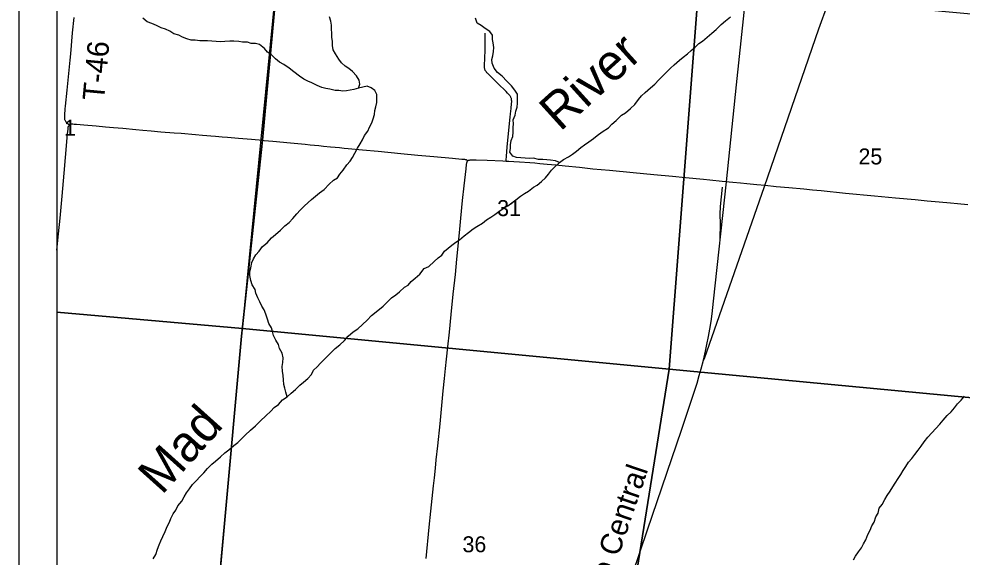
# Model space of a CAD drawing. Extents: x 831 to 1552, y 430 to 870.
# Drawn here: x 943.77 to 993.28, y 749.13 to 777.36 of the extents above; entities that cross this region are included whole.
import ezdxf

# ---------------------------------------------------------------- set-up
doc = ezdxf.new("R2010")
doc.units = 0
for name, color, linetype in [('GM_X_Corporation', 7, 'Continuous'), ('GM_X_County_Road', 7, 'Continuous'), ('GM_X_Major_River', 7, 'Continuous'), ('GM_X_Major_River_Text', 7, 'Continuous'), ('GM_X_Minor_River', 7, 'Continuous'), ('GM_X_Rail_Line', 7, 'Continuous'), ('GM_X_Rail_Line_Text', 7, 'Continuous'), ('GM_X_Section_Text', 7, 'Continuous'), ('GM_X_Township_Road', 7, 'Continuous'), ('GM_X_Township_Road_Text', 7, 'Continuous'), ('SH_Data', 7, 'Continuous')]:
    doc.layers.add(name, color=color, linetype=linetype)

msp = doc.modelspace()

# ---------------------------------------------------------------- linework, layer by layer
at = {"layer": 'GM_X_Corporation'}
for points in [[(958.1, 786.938), (945.766, 786.938), (945.766, 741.831), (953.653, 740.871), (955.451, 760.717), (956.56, 771.006), (957.479, 781.045), (957.492, 781.063), (957.507, 781.085), (957.522, 781.111), (957.532, 781.136), (957.541, 781.164), (957.55, 781.197), (957.556, 781.228), (957.562, 781.276), (957.568, 781.33), (957.577, 781.435), (957.589, 781.599), (957.656, 782.366), (957.749, 783.356), (957.89, 784.782), (957.984, 785.755), (958.044, 786.336)], [(945.766, 781.984), (945.766, 761.978), (955.51, 761.115), (957.457, 780.993)], [(979.447, 778.955), (977.893, 758.996), (955.51, 761.115), (957.457, 780.993)], [(998.895, 777.157), (996.953, 757.185), (977.893, 758.996), (979.447, 778.955)], [(945.766, 761.978), (945.766, 741.664), (953.634, 740.857), (955.51, 761.115)], [(977.893, 758.996), (974.695, 738.984), (953.634, 740.857), (955.51, 761.115)], [(996.953, 757.185), (994.975, 737.085), (974.695, 738.984), (977.893, 758.996)]]:
    msp.add_lwpolyline(points, close=True, dxfattribs=at)
msp.add_lwpolyline([(957.479, 781.045), (956.56, 771.006), (955.451, 760.717), (953.653, 740.871), (952.689, 730.885), (949.971, 703.401), (947.763, 681.071), (945.766, 658.183), (945.766, 650.938), (1069.909, 650.938), (1070.34, 654.531), (1072.813, 675.454), (1078.126, 715.958), (1081.227, 740.59), (1081.766, 744.853), (1081.766, 786.938)], dxfattribs=at)
at = {"layer": 'GM_X_County_Road'}
for points in [[(945.766, 765.229), (945.854, 766.095), (945.934, 766.917), (946.044, 768.07), (946.148, 769.277), (946.215, 770.089), (946.326, 771.327), (946.346, 771.583), (946.351, 771.628), (946.353, 771.651), (946.357, 771.674), (946.362, 771.692), (946.366, 771.707), (946.371, 771.72), (946.377, 771.732), (946.384, 771.743), (946.393, 771.755), (946.402, 771.764), (946.422, 771.782)], [(946.422, 771.782), (946.441, 771.798), (946.456, 771.81), (946.473, 771.825), (946.486, 771.832), (946.5, 771.838), (946.512, 771.843), (946.532, 771.848), (946.553, 771.85), (946.601, 771.849), (946.665, 771.846), (946.79, 771.838), (947.173, 771.806), (947.819, 771.751), (948.31, 771.704), (948.741, 771.667), (949.215, 771.626), (949.907, 771.565), (950.273, 771.532), (950.706, 771.491), (951.224, 771.445), (951.911, 771.39), (952.283, 771.361), (953.031, 771.3), (953.407, 771.269), (953.638, 771.249), (953.841, 771.231), (954.093, 771.208), (954.431, 771.18), (954.709, 771.155), (955.296, 771.104), (955.973, 771.048), (956.565, 770.995)], [(956.565, 770.995), (956.634, 770.989), (957.088, 770.948), (958.025, 770.863), (958.793, 770.787), (959.048, 770.762), (959.516, 770.718), (959.76, 770.693), (960.126, 770.656), (960.368, 770.631), (960.587, 770.608), (960.833, 770.585), (961.055, 770.562), (961.805, 770.491), (962.622, 770.417), (963.822, 770.301), (964.701, 770.217), (965.555, 770.138), (966.519, 770.052), (967.014, 770.01), (967.074, 770.005), (967.148, 769.998), (967.196, 769.992), (967.217, 769.988), (967.238, 769.982), (967.254, 769.975), (967.268, 769.967), (967.283, 769.955), (967.298, 769.943), (967.332, 769.913)], [(965.136, 749.053), (965.307, 750.7), (965.394, 751.549), (965.527, 752.866), (965.575, 753.296), (965.629, 753.789), (965.677, 754.235), (965.749, 754.963), (965.871, 756.122), (965.93, 756.698), (966.042, 757.844), (966.106, 758.493), (966.157, 759.032), (966.211, 759.516), (966.282, 760.165), (966.367, 760.934), (966.461, 761.862), (966.57, 762.922), (966.677, 763.961), (966.755, 764.755), (966.861, 765.784), (966.918, 766.338), (966.971, 766.915), (967.058, 767.829), (967.143, 768.597), (967.241, 769.502), (967.265, 769.729), (967.27, 769.765), (967.275, 769.792), (967.283, 769.827), (967.292, 769.853), (967.301, 769.873), (967.311, 769.889), (967.322, 769.903), (967.332, 769.913)], [(967.332, 769.913), (967.353, 769.931), (967.373, 769.942), (967.394, 769.95), (967.42, 769.957), (967.447, 769.962), (967.479, 769.965), (967.532, 769.967), (967.61, 769.965), (967.768, 769.962), (968.344, 769.942), (969.174, 769.913), (969.338, 769.905)], [(969.338, 769.905), (969.486, 769.898), (969.748, 769.883), (970.037, 769.866), (970.583, 769.83), (970.841, 769.809), (971.102, 769.784), (971.503, 769.743), (971.942, 769.702), (972.444, 769.651), (973.197, 769.576), (973.897, 769.503), (974.765, 769.418), (976.011, 769.301), (977.087, 769.199), (978.076, 769.107), (978.752, 769.04), (979.699, 768.947), (980.025, 768.915), (980.685, 768.851), (981.234, 768.798), (981.647, 768.758), (981.979, 768.726), (982.497, 768.675), (982.934, 768.632), (983.507, 768.576), (984.174, 768.512), (984.96, 768.439), (985.422, 768.395), (985.872, 768.351), (987.155, 768.226), (988.672, 768.081), (989.772, 767.979), (990.808, 767.884), (991.436, 767.825), (992.072, 767.764), (992.667, 767.708), (993.037, 767.675), (993.579, 767.622)]]:
    msp.add_lwpolyline(points, dxfattribs=at)
at = {"layer": 'GM_X_Major_River'}
for points in [[(968.756, 767.099), (968.965, 767.253), (969.19, 767.421), (969.429, 767.559), (969.647, 767.72), (969.856, 767.874), (970.097, 768.057), (970.314, 768.21), (970.514, 768.326), (970.771, 768.532), (970.979, 768.647), (971.205, 768.831), (971.408, 769.023), (971.573, 769.224), (971.731, 769.425), (971.919, 769.625), (972.144, 769.823), (972.354, 769.985), (972.616, 770.122), (972.833, 770.26), (973.035, 770.421), (973.26, 770.613), (973.462, 770.759), (973.679, 770.92), (973.919, 771.08), (974.122, 771.249), (974.385, 771.44), (974.71, 771.643), (974.882, 771.836), (975.116, 772.027), (975.405, 772.308), (975.613, 772.431), (975.863, 772.667), (976.089, 772.874), (976.294, 773.127), (976.444, 773.32), (976.646, 773.505), (976.927, 773.748), (977.145, 773.939), (977.364, 774.169), (977.544, 774.361), (977.74, 774.554), (977.966, 774.775), (978.161, 774.952), (978.434, 775.203), (978.628, 775.35), (978.853, 775.526), (979.048, 775.695), (979.243, 775.857), (979.454, 776.064), (979.647, 776.195), (979.888, 776.401), (980.13, 776.615), (980.371, 776.806), (980.629, 777.065), (980.862, 777.263), (981.119, 777.477)], [(950.823, 749.04), (950.952, 749.272), (951.043, 749.543), (951.126, 749.783), (951.223, 749.978), (951.328, 750.211), (951.442, 750.473), (951.549, 750.736), (951.669, 750.961), (951.751, 751.164), (951.872, 751.396), (951.999, 751.59), (952.104, 751.815), (952.324, 752.059), (952.437, 752.284), (952.564, 752.5), (952.715, 752.716), (952.881, 752.947), (953.084, 753.154), (953.257, 753.347), (953.476, 753.553), (953.665, 753.783), (953.891, 754.004), (954.086, 754.166), (954.35, 754.386), (954.584, 754.6), (954.793, 754.753), (955.043, 754.982), (955.253, 755.15), (955.448, 755.335), (955.636, 755.534), (955.924, 755.784), (956.189, 756.012), (956.455, 756.278), (956.736, 756.544), (956.993, 756.779), (957.166, 756.972), (957.391, 757.14), (957.61, 757.377), (957.843, 757.545), (958.053, 757.737), (958.294, 757.92), (958.513, 758.141), (958.708, 758.303), (958.933, 758.502), (959.129, 758.709), (959.227, 758.942), (959.422, 759.119), (959.602, 759.311), (959.829, 759.533), (960.103, 759.814), (960.376, 760.072), (960.617, 760.263), (960.851, 760.484), (961.047, 760.714), (961.312, 760.942), (961.552, 761.11), (961.802, 761.338), (962.043, 761.552), (962.279, 761.804), (962.527, 762.002), (962.885, 762.296), (963.112, 762.525), (963.33, 762.724), (963.555, 762.892), (963.749, 763.046), (963.999, 763.282), (964.192, 763.398), (964.357, 763.591), (964.575, 763.768), (964.816, 763.974), (965.045, 764.264), (965.276, 764.371), (965.564, 764.636), (965.767, 764.828), (965.969, 764.967), (966.111, 765.176), (966.306, 765.338), (966.5, 765.484), (966.694, 765.646), (966.888, 765.777), (967.137, 765.975), (967.369, 766.151), (967.618, 766.342), (967.812, 766.48), (968.097, 766.647), (968.315, 766.823), (968.539, 766.969), (968.756, 767.099)]]:
    msp.add_lwpolyline(points, dxfattribs=at)
at = {"layer": 'GM_X_Minor_River'}
for points in [[(956.183, 776.072), (955.962, 776.064), (955.767, 776.131), (955.509, 776.131), (955.305, 776.167), (955.055, 776.197), (954.835, 776.196), (954.569, 776.166), (954.341, 776.15), (954.121, 776.172), (953.894, 776.194), (953.674, 776.208), (953.447, 776.207), (953.257, 776.213), (953.023, 776.243), (952.818, 776.249), (952.577, 776.317), (952.36, 776.407), (952.158, 776.505), (951.901, 776.573), (951.685, 776.709), (951.461, 776.822), (951.243, 776.89), (950.996, 777.019), (950.749, 777.125), (950.508, 777.201), (950.279, 777.398)], [(961.587, 773.726), (961.668, 773.929), (961.629, 774.151), (961.492, 774.376), (961.278, 774.603), (961.086, 774.761), (960.892, 774.881), (960.699, 775.047), (960.569, 775.249), (960.379, 775.521), (960.271, 775.73), (960.233, 775.967), (960.224, 776.173), (960.2, 776.41), (960.191, 776.608), (960.182, 776.829), (960.173, 777.035), (960.141, 777.249), (960.079, 777.472)], [(972.144, 769.823), (971.927, 769.921), (971.67, 769.952), (971.473, 769.973), (971.276, 769.986), (971.033, 769.978), (970.77, 770.055), (970.549, 770.039), (970.345, 770.06), (970.118, 770.074), (969.883, 770.089), (969.687, 770.156), (969.542, 770.373), (969.563, 770.571), (969.568, 770.761), (969.598, 770.981), (969.695, 771.199), (969.717, 771.419), (969.716, 771.663), (969.73, 771.86), (969.713, 772.066), (969.811, 772.307), (969.855, 772.512), (969.914, 772.723), (969.943, 772.943), (969.943, 773.21), (969.934, 773.415), (969.804, 773.625), (969.621, 773.851), (969.385, 774.087), (969.134, 774.353), (968.889, 774.543), (968.714, 774.777), (968.6, 775.032), (968.59, 775.222), (968.642, 775.419), (968.686, 775.646), (968.7, 775.859), (968.661, 776.096), (968.621, 776.288), (968.62, 776.509), (968.482, 776.703), (968.244, 776.863), (968.036, 777.021), (967.827, 777.142), (967.735, 777.396)], [(957.843, 757.545), (957.774, 757.783), (957.719, 757.99), (957.679, 758.182), (957.649, 758.434), (957.64, 758.662), (957.601, 758.892), (957.593, 759.136), (957.622, 759.333), (957.644, 759.583), (957.591, 759.836), (957.454, 760.068), (957.399, 760.283), (957.247, 760.516), (957.14, 760.748), (957.078, 760.963), (957.023, 761.162), (956.892, 761.379), (956.816, 761.61), (956.725, 761.871), (956.633, 762.102), (956.524, 762.296), (956.417, 762.52), (956.309, 762.729), (956.21, 762.968), (956.163, 763.159), (956.018, 763.407), (955.941, 763.638), (955.896, 763.906), (955.887, 764.112), (955.938, 764.308), (955.992, 764.588), (956.089, 764.783), (956.201, 764.993), (956.374, 765.186), (956.555, 765.424), (956.796, 765.615), (957.031, 765.874), (957.241, 766.043), (957.498, 766.271), (957.718, 766.501), (957.95, 766.676), (958.139, 766.884), (958.351, 767.129), (958.538, 767.321), (958.765, 767.55), (959.124, 767.89), (959.334, 768.059), (959.544, 768.235), (959.785, 768.418), (960.051, 768.685), (960.277, 768.899), (960.493, 769.029), (960.62, 769.223), (960.786, 769.424), (960.976, 769.7), (961.149, 769.901), (961.276, 770.095), (961.404, 770.319), (961.548, 770.574), (961.684, 770.814), (961.796, 771.023), (961.909, 771.249), (962.083, 771.472), (962.165, 771.683), (962.285, 771.9), (962.367, 772.126), (962.427, 772.353), (962.456, 772.55), (962.5, 772.754), (962.552, 772.981), (962.558, 773.202), (962.556, 773.392), (962.448, 773.601), (962.255, 773.751), (962.045, 773.826), (961.824, 773.787), (961.587, 773.726), (961.349, 773.649), (960.968, 773.592), (960.77, 773.575), (960.559, 773.612), (960.369, 773.61), (960.09, 773.679), (959.886, 773.715), (959.675, 773.767), (959.428, 773.866), (959.151, 774.012), (958.941, 774.094), (958.732, 774.207), (958.501, 774.351), (958.204, 774.581), (957.951, 774.771), (957.676, 774.962), (957.444, 775.091), (957.237, 775.272), (957.016, 775.499), (956.815, 775.62), (956.653, 775.815), (956.394, 776.013), (956.183, 776.072)], [(987.581, 748.984), (987.685, 749.178), (987.836, 749.402), (987.994, 749.626), (988.106, 749.82), (988.226, 750.03), (988.333, 750.315), (988.454, 750.548), (988.544, 750.773), (988.656, 750.968), (988.747, 751.239), (988.86, 751.441), (988.92, 751.69), (989.07, 751.899), (989.215, 752.161), (989.342, 752.37), (989.5, 752.586), (989.643, 752.81), (989.763, 753.004), (989.915, 753.259), (990.05, 753.468), (990.177, 753.677), (990.32, 753.878), (990.455, 754.103), (990.628, 754.31), (990.801, 754.511), (990.967, 754.742), (991.126, 754.958), (991.284, 755.181), (991.473, 755.427), (991.684, 755.641), (991.896, 755.879), (992.1, 756.101), (992.288, 756.308), (992.485, 756.554), (992.696, 756.753), (992.877, 756.968), (993.027, 757.162), (993.222, 757.362), (993.403, 757.569)]]:
    msp.add_lwpolyline(points, dxfattribs=at)
at = {"layer": 'GM_X_Rail_Line'}
for points in [[(987.911, 786.938), (987.914, 786.515), (987.926, 784.591), (987.734, 783.273), (987.514, 782.286), (987.116, 780.763), (986.674, 779.43), (985.738, 776.813), (982.879, 768.559), (979.733, 759.534), (979.672, 759.393)], [(974.776, 744.729), (976.758, 750.569), (978.54, 755.793), (979.212, 757.788), (979.363, 758.249), (979.482, 758.658), (979.576, 759.002), (979.697, 759.461), (979.811, 759.931), (979.883, 760.281), (979.97, 760.704), (980.032, 761.081), (980.099, 761.483), (980.151, 761.884), (980.23, 762.56), (980.903, 768.82), (981.438, 773.906), (982.368, 782.66)], [(980.582, 765.835), (980.59, 766.603), (980.573, 767.113), (980.59, 767.527), (980.698, 768.543)]]:
    msp.add_lwpolyline(points, dxfattribs=at)
at = {"layer": 'GM_X_Township_Road'}
for points in [[(946.422, 771.782), (946.352, 771.844), (946.311, 771.881), (946.277, 771.918), (946.253, 771.948), (946.233, 771.978), (946.214, 772.006), (946.2, 772.034), (946.186, 772.067), (946.178, 772.105), (946.175, 772.149), (946.173, 772.188), (946.173, 772.23), (946.174, 772.273), (946.178, 772.353), (946.183, 772.426), (946.19, 772.514), (946.203, 772.638), (946.219, 772.789), (946.303, 773.619), (946.367, 774.316), (946.454, 775.197), (946.486, 775.528), (946.584, 776.631), (946.661, 777.433)], [(969.338, 769.905), (969.341, 769.951), (969.354, 770.165), (969.398, 770.63), (969.507, 771.697), (969.558, 772.205), (969.574, 772.381), (969.604, 772.665), (969.629, 772.92), (969.631, 772.963), (969.633, 773), (969.633, 773.044), (969.632, 773.09), (969.63, 773.117), (969.627, 773.135), (969.623, 773.156), (969.617, 773.182), (969.608, 773.203), (969.596, 773.23), (969.584, 773.257), (969.569, 773.284), (969.553, 773.308), (969.534, 773.335), (969.501, 773.376), (969.466, 773.416), (969.417, 773.469), (969.341, 773.547), (969.239, 773.649), (969.018, 773.862), (968.73, 774.141), (968.464, 774.402), (968.365, 774.506), (968.337, 774.537), (968.308, 774.57), (968.286, 774.596), (968.269, 774.619), (968.259, 774.634), (968.247, 774.654), (968.236, 774.679), (968.227, 774.704), (968.219, 774.736), (968.213, 774.772), (968.21, 774.813), (968.21, 774.859), (968.212, 774.915), (968.225, 775.303), (968.229, 775.452), (968.233, 775.557), (968.244, 775.991), (968.245, 776.285), (968.245, 776.496), (968.245, 776.608)]]:
    msp.add_lwpolyline(points, dxfattribs=at)
at = {"layer": 'SH_Data'}
for p, q in [((943.766, 788.938), (943.766, 648.938)), ((945.766, 786.938), (945.766, 650.938))]:
    msp.add_line(p, q, dxfattribs=at)

# ---------------------------------------------------------------- texts
at = {"layer": 'GM_X_Major_River_Text'}
for s, height, rotation, p in [('River', 1.8937, 42.1556, (972.174, 771.415)), ('Mad', 1.8921, 48.1122, (951.274, 752.348))]:
    msp.add_text(s, height=height, rotation=rotation, dxfattribs=at).set_placement(p)
at = {"layer": 'GM_X_Rail_Line_Text'}
msp.add_text('Indiana & Ohio Central', height=1.13258, rotation=71.2044, dxfattribs=at).set_placement((971.871, 739.23))
at = {"layer": 'GM_X_Section_Text'}
for s, height, p in [('1', 0.837, (946.138, 771.235)), ('25', 0.8371, (987.838, 769.727)), ('31', 0.8371, (968.871, 767.018)), ('36', 0.8371, (967.054, 749.385))]:
    msp.add_text(s, height=height, rotation=0, dxfattribs=at).set_placement(p)
at = {"layer": 'GM_X_Township_Road_Text'}
msp.add_text('T-46', height=1.1364, rotation=84.7098, dxfattribs=at).set_placement((948.235, 773.036))

doc.saveas('drawing.dxf')
